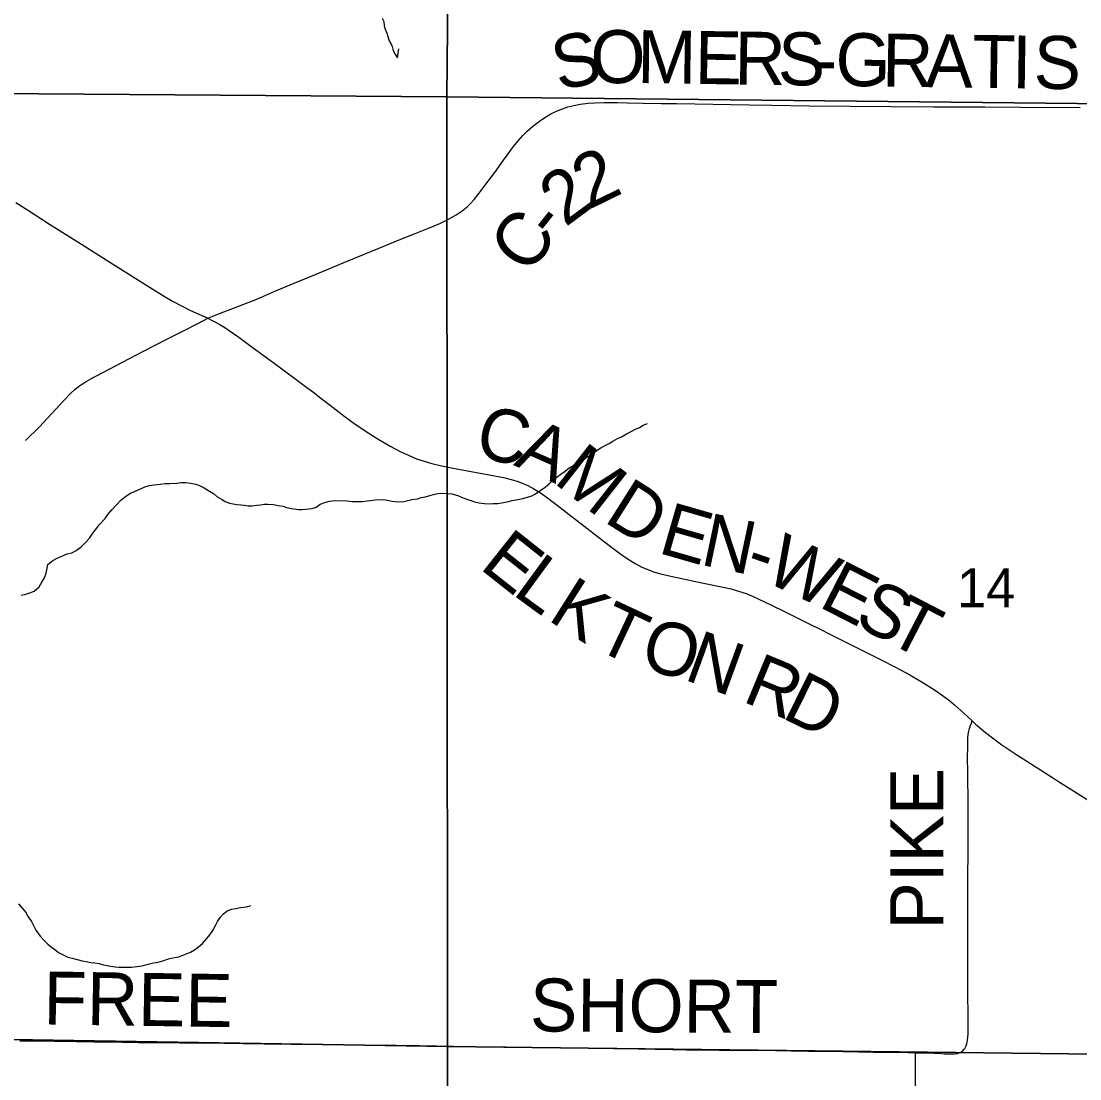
# Model space of a CAD drawing. Extents: x -8.8 to 41.4, y 0 to 34.6.
# Drawn here: x -7.904 to -6.769, y 15.544 to 16.678 of the extents above; entities that cross this region are included whole.
import ezdxf

# ---------------------------------------------------------------- set-up
doc = ezdxf.new("R2010")
doc.units = 0
for name, color, linetype in [('GM_X_Corporation', 7, 'Continuous'), ('GM_X_County_Road', 7, 'Continuous'), ('GM_X_Minor_River', 7, 'Continuous'), ('GM_X_Section_Text', 7, 'Continuous'), ('GM_X_Township_Road', 7, 'Continuous'), ('GM_X_Township_Road_Text', 7, 'Continuous'), ('GM_X_Township_Text', 7, 'Continuous')]:
    doc.layers.add(name, color=color, linetype=linetype)

msp = doc.modelspace()

# ---------------------------------------------------------------- linework, layer by layer
at = {"layer": 'GM_X_Corporation'}
for points in [[(-8.3984, 17.6086), (-7.4378, 17.5869), (-7.4474, 16.5968), (-8.42, 16.6037)], [(-7.4378, 17.5869), (-6.4092, 17.5696), (-6.4339, 16.586), (-7.4474, 16.5968)], [(-8.42, 16.6037), (-7.4474, 16.5968), (-7.4468, 15.5783), (-8.4261, 15.5941)], [(-7.4474, 16.5968), (-6.4339, 16.586), (-6.4479, 15.5667), (-7.4468, 15.5783)], [(-8.4261, 15.5941), (-7.4468, 15.5783), (-7.4475, 14.5649), (-8.4246, 14.5962)], [(-6.4479, 15.5667), (-6.4506, 14.5538), (-7.4475, 14.5649), (-7.4468, 15.5783)]]:
    msp.add_lwpolyline(points, close=True, dxfattribs=at)
at = {"layer": 'GM_X_County_Road'}
for points in [[(-7.7038, 16.3592), (-7.6912, 16.3642), (-7.6745, 16.3708), (-7.6514, 16.3799), (-7.6321, 16.3882), (-7.6051, 16.3993), (-7.5919, 16.4047), (-7.5586, 16.4186), (-7.5132, 16.4373), (-7.4987, 16.4432), (-7.4816, 16.4501), (-7.4671, 16.4558), (-7.4551, 16.461), (-7.4451, 16.4659), (-7.4374, 16.4702), (-7.4311, 16.4744), (-7.4258, 16.4788), (-7.4222, 16.4823), (-7.4184, 16.4865), (-7.413, 16.4933), (-7.4032, 16.5062), (-7.3962, 16.5157), (-7.3868, 16.5288), (-7.376, 16.5433), (-7.3711, 16.5496), (-7.3662, 16.5552), (-7.3614, 16.5599), (-7.3558, 16.5648), (-7.3495, 16.5697), (-7.3434, 16.5739), (-7.336, 16.5783), (-7.33, 16.5813), (-7.3237, 16.5839), (-7.3179, 16.5858), (-7.3113, 16.5875), (-7.3047, 16.5888), (-7.2961, 16.5899), (-7.2887, 16.5904), (-7.2788, 16.5906), (-7.2646, 16.5905), (-7.254, 16.5902), (-7.2372, 16.59), (-7.2177, 16.5897), (-7.2012, 16.5894), (-7.1232, 16.5882), (-7.099, 16.5878), (-7.0586, 16.5872), (-7.015, 16.5866), (-6.9716, 16.5863), (-6.9259, 16.586), (-6.9046, 16.5859), (-6.8709, 16.5858), (-6.8324, 16.5857), (-6.7685, 16.5853)], [(-7.9097, 16.4834), (-7.897, 16.4755), (-7.8735, 16.4603), (-7.8363, 16.4368), (-7.8126, 16.4219), (-7.7684, 16.3942), (-7.7495, 16.3824), (-7.7415, 16.3776), (-7.7312, 16.3721), (-7.7223, 16.3676), (-7.711, 16.3624), (-7.7038, 16.3592), (-7.7014, 16.3581), (-7.697, 16.3558), (-7.6909, 16.3525), (-7.6867, 16.35), (-7.682, 16.3468), (-7.6707, 16.339), (-7.6561, 16.3284), (-7.6341, 16.3122), (-7.6092, 16.2937), (-7.5977, 16.2851), (-7.5903, 16.2795), (-7.5839, 16.2746), (-7.5741, 16.267), (-7.5662, 16.2609), (-7.5564, 16.2534), (-7.5458, 16.2458), (-7.5376, 16.2402), (-7.5319, 16.2365), (-7.5203, 16.2293), (-7.5075, 16.2218), (-7.4976, 16.2165), (-7.4881, 16.212), (-7.4802, 16.2087), (-7.472, 16.2059), (-7.4637, 16.2035), (-7.4547, 16.2014), (-7.4388, 16.1983), (-7.4022, 16.1914), (-7.3869, 16.1884), (-7.3784, 16.1863), (-7.3712, 16.1841), (-7.3659, 16.1822), (-7.3608, 16.1799), (-7.3541, 16.1764), (-7.3472, 16.1721), (-7.3395, 16.1668), (-7.3262, 16.1565), (-7.3165, 16.1489), (-7.2738, 16.1159), (-7.2609, 16.1063), (-7.2522, 16.1004), (-7.2449, 16.0959), (-7.2384, 16.0924), (-7.2322, 16.0897), (-7.2258, 16.0875), (-7.2169, 16.085), (-7.2024, 16.0815), (-7.1811, 16.0771), (-7.1549, 16.0718), (-7.1428, 16.069), (-7.1349, 16.0668), (-7.1267, 16.064), (-7.1192, 16.0609), (-7.1129, 16.0581), (-7.0995, 16.0516), (-7.0855, 16.0448), (-7.0605, 16.0323), (-7.0466, 16.0254), (-7.0371, 16.0206), (-7.0149, 16.0096), (-6.9999, 16.0021), (-6.9826, 15.9935), (-6.9666, 15.9852), (-6.9513, 15.9769), (-6.9363, 15.968), (-6.9247, 15.9607), (-6.9149, 15.9541), (-6.9084, 15.9492), (-6.9032, 15.9448), (-6.893, 15.9356), (-6.8898, 15.9325), (-6.8842, 15.9275)], [(-6.8842, 15.9275), (-6.883, 15.9263), (-6.8807, 15.9241), (-6.8773, 15.9211), (-6.8719, 15.9164), (-6.8626, 15.9092), (-6.8526, 15.9019), (-6.8366, 15.8913), (-6.8109, 15.8749), (-6.7889, 15.8609), (-6.7563, 15.8403)]]:
    msp.add_lwpolyline(points, dxfattribs=at)
at = {"layer": 'GM_X_Minor_River'}
for points in [[(-7.517, 16.681), (-7.5152, 16.6775), (-7.5146, 16.6729), (-7.5136, 16.6694), (-7.5118, 16.6648), (-7.5094, 16.6568), (-7.5076, 16.6537), (-7.5062, 16.6506), (-7.5049, 16.6463), (-7.5027, 16.6417), (-7.5006, 16.6386), (-7.4991, 16.648)], [(-7.6685, 16.1592), (-7.6648, 16.1587), (-7.6606, 16.1581), (-7.6564, 16.158), (-7.6511, 16.1589), (-7.6473, 16.1592), (-7.6434, 16.1598), (-7.6396, 16.16), (-7.6332, 16.1594), (-7.6283, 16.1585), (-7.623, 16.1576), (-7.6189, 16.1563), (-7.6139, 16.1553), (-7.6064, 16.1543), (-7.6026, 16.1542), (-7.5919, 16.1553), (-7.5877, 16.1567), (-7.5834, 16.1599), (-7.5772, 16.162), (-7.5734, 16.163), (-7.5676, 16.1639), (-7.5544, 16.1635), (-7.549, 16.1629), (-7.5449, 16.1627), (-7.5384, 16.1629), (-7.5331, 16.1635), (-7.5293, 16.1637), (-7.5243, 16.1647), (-7.5151, 16.1651), (-7.5061, 16.1633), (-7.5, 16.1623), (-7.4936, 16.1628), (-7.4851, 16.1648), (-7.479, 16.1657), (-7.4752, 16.1671), (-7.4709, 16.1677), (-7.4667, 16.1687), (-7.4617, 16.1704), (-7.4571, 16.1714), (-7.4522, 16.1716), (-7.4472, 16.1714), (-7.4423, 16.1709), (-7.4359, 16.1691), (-7.4311, 16.167), (-7.4262, 16.1653), (-7.4217, 16.1637), (-7.4179, 16.1624), (-7.413, 16.1614), (-7.4073, 16.1605), (-7.4028, 16.1603), (-7.3978, 16.1605), (-7.3929, 16.1607), (-7.3891, 16.1613), (-7.3829, 16.1623), (-7.3776, 16.164), (-7.3715, 16.1649), (-7.3661, 16.1659), (-7.3622, 16.1672), (-7.3565, 16.1689), (-7.3526, 16.1711), (-7.3475, 16.1747), (-7.3436, 16.1772), (-7.3382, 16.1812), (-7.3342, 16.1853), (-7.3291, 16.1893), (-7.3252, 16.1922), (-7.3206, 16.1954), (-7.3163, 16.1987), (-7.3124, 16.2012), (-7.3077, 16.2041), (-7.3023, 16.2069), (-7.2972, 16.2106), (-7.2925, 16.213), (-7.2875, 16.2171), (-7.2824, 16.2203), (-7.2785, 16.2224), (-7.2735, 16.2249), (-7.2696, 16.2274), (-7.2646, 16.2303), (-7.2603, 16.2321), (-7.2549, 16.2353), (-7.2498, 16.2378), (-7.2452, 16.2403), (-7.2409, 16.242), (-7.2371, 16.2445), (-7.2324, 16.2463)], [(-7.9039, 16.0622), (-7.9001, 16.0632), (-7.8947, 16.065), (-7.8901, 16.0667), (-7.8846, 16.0711), (-7.8818, 16.0763), (-7.8789, 16.0811), (-7.8772, 16.086), (-7.8759, 16.0913), (-7.8754, 16.0951), (-7.8699, 16.0994), (-7.8652, 16.1019), (-7.8602, 16.104), (-7.8544, 16.1065), (-7.8494, 16.1078), (-7.8448, 16.1103), (-7.8397, 16.114), (-7.8346, 16.1191), (-7.8306, 16.1235), (-7.827, 16.1287), (-7.823, 16.1339), (-7.8198, 16.138), (-7.8139, 16.1446), (-7.8111, 16.1487), (-7.8063, 16.1542), (-7.802, 16.159), (-7.7969, 16.1642), (-7.7918, 16.1685), (-7.7867, 16.1718), (-7.7825, 16.1735), (-7.7774, 16.1756), (-7.7713, 16.1785), (-7.7663, 16.1798), (-7.7613, 16.1808), (-7.7548, 16.1813), (-7.7495, 16.1819), (-7.7445, 16.1821), (-7.7369, 16.1826), (-7.7327, 16.1832), (-7.7274, 16.183), (-7.7221, 16.1824), (-7.7168, 16.1815), (-7.7127, 16.1798), (-7.7078, 16.1773), (-7.7019, 16.1737), (-7.6978, 16.1713), (-7.6941, 16.1681), (-7.6892, 16.1653), (-7.6851, 16.1628), (-7.6806, 16.1611), (-7.6765, 16.1602), (-7.6727, 16.1597), (-7.6685, 16.1592)], [(-7.9067, 15.7314), (-7.9027, 15.7267), (-7.8987, 15.7216), (-7.8966, 15.7177), (-7.8933, 15.713), (-7.8908, 15.708), (-7.888, 15.7033), (-7.8836, 15.6967), (-7.8796, 15.6924), (-7.8752, 15.688), (-7.8715, 15.6849), (-7.8678, 15.6824), (-7.8637, 15.6793), (-7.854, 15.6743), (-7.8491, 15.673), (-7.8423, 15.6713), (-7.8386, 15.6704), (-7.8337, 15.6694), (-7.8291, 15.6685), (-7.825, 15.668), (-7.8204, 15.6674), (-7.8155, 15.6661), (-7.8118, 15.6652), (-7.808, 15.6647), (-7.8031, 15.6638), (-7.7993, 15.6633), (-7.7955, 15.6635), (-7.7906, 15.6633), (-7.7856, 15.6635), (-7.7772, 15.6647), (-7.7726, 15.6653), (-7.7676, 15.6667), (-7.7619, 15.668), (-7.7569, 15.669), (-7.7519, 15.6703), (-7.7461, 15.6724), (-7.7396, 15.6737), (-7.735, 15.6746), (-7.7296, 15.6767), (-7.7223, 15.6795), (-7.718, 15.682), (-7.7137, 15.6853), (-7.7094, 15.6889), (-7.7047, 15.6941), (-7.7015, 15.6982), (-7.6983, 15.7026), (-7.6954, 15.7082), (-7.6934, 15.7123), (-7.6906, 15.7168), (-7.687, 15.7205), (-7.6831, 15.7238), (-7.6785, 15.7255), (-7.6739, 15.7265), (-7.6689, 15.7274), (-7.6624, 15.7283), (-7.6578, 15.7297)]]:
    msp.add_lwpolyline(points, dxfattribs=at)
at = {"layer": 'GM_X_Township_Road'}
for points in [[(-7.8992, 16.2281), (-7.8844, 16.2429), (-7.8581, 16.2711), (-7.8508, 16.2788), (-7.8463, 16.283), (-7.8424, 16.2861), (-7.8383, 16.289), (-7.8341, 16.2915), (-7.8253, 16.2963), (-7.8149, 16.3018), (-7.7886, 16.3159), (-7.772, 16.3245), (-7.7476, 16.3368), (-7.7299, 16.3458), (-7.7139, 16.354), (-7.7038, 16.3592)], [(-6.945, 15.5717), (-6.933, 15.5715), (-6.9175, 15.5709), (-6.9144, 15.5707), (-6.9107, 15.5705), (-6.9068, 15.5704), (-6.9031, 15.5706), (-6.9, 15.571), (-6.8975, 15.5718), (-6.8958, 15.5728), (-6.8943, 15.5739), (-6.893, 15.5754), (-6.8923, 15.5763), (-6.8914, 15.5776), (-6.8907, 15.5792), (-6.8899, 15.5816), (-6.8892, 15.5853), (-6.8889, 15.5885), (-6.8887, 15.5915), (-6.8886, 15.6006), (-6.8888, 15.6155), (-6.889, 15.6314), (-6.889, 15.6501), (-6.889, 15.6709), (-6.889, 15.6818), (-6.889, 15.6979), (-6.889, 15.7116), (-6.889, 15.7221), (-6.8889, 15.7417), (-6.8889, 15.7606), (-6.8888, 15.7861), (-6.8888, 15.8103), (-6.8888, 15.8336), (-6.8888, 15.8501), (-6.8889, 15.8598), (-6.8891, 15.8722), (-6.8893, 15.8888), (-6.8891, 15.8986), (-6.889, 15.9091), (-6.8885, 15.9129), (-6.8879, 15.9166), (-6.8871, 15.9195), (-6.886, 15.9226), (-6.8851, 15.9251), (-6.8842, 15.9275)], [(-7.9054, 15.5845), (-7.8967, 15.5844), (-7.8905, 15.5844), (-7.8756, 15.5843), (-7.8682, 15.5842), (-7.8589, 15.5841), (-7.8446, 15.5838), (-7.826, 15.5834), (-7.7956, 15.583), (-7.7856, 15.5829), (-7.7782, 15.5828), (-7.7533, 15.5827), (-7.7335, 15.5824), (-7.7173, 15.5822), (-7.7074, 15.5821), (-7.695, 15.5822), (-7.6863, 15.5818), (-7.6664, 15.5815), (-7.6434, 15.5813), (-7.6279, 15.5811), (-7.6149, 15.5809), (-7.5807, 15.5806), (-7.5596, 15.5804), (-7.5472, 15.5802), (-7.526, 15.5799), (-7.5018, 15.5797), (-7.477, 15.5793), (-7.4404, 15.5789), (-7.4193, 15.5784), (-7.3839, 15.5779), (-7.3472, 15.5774), (-7.3274, 15.5772), (-7.3093, 15.5771), (-7.2808, 15.5765), (-7.2684, 15.5764), (-7.2615, 15.5764), (-7.2491, 15.5762), (-7.2423, 15.576), (-7.2361, 15.5759), (-7.2243, 15.5757), (-7.2175, 15.5756), (-7.2057, 15.5753), (-7.1988, 15.5752), (-7.1908, 15.575), (-7.1852, 15.575), (-7.1715, 15.5748), (-7.1554, 15.5745), (-7.1405, 15.5744), (-7.1218, 15.5743), (-7.0951, 15.5741), (-7.0783, 15.5738), (-7.0597, 15.5735), (-7.0516, 15.5733), (-7.0225, 15.573), (-6.9902, 15.5724), (-6.9734, 15.5722), (-6.9666, 15.5722), (-6.9529, 15.5719), (-6.945, 15.5717)], [(-6.9452, 15.5357), (-6.9451, 15.5547), (-6.945, 15.5651), (-6.945, 15.5717)]]:
    msp.add_lwpolyline(points, dxfattribs=at)

# ---------------------------------------------------------------- texts
at = {"layer": 'GM_X_Section_Text'}
for s, rotation, p in [('PIKE', 90, (-6.9154, 15.7039)), ('FREE', 359.1574, (-7.8802, 15.6021)), ('SHORT', 359.5955, (-7.3585, 15.5946))]:
    msp.add_text(s, height=0.05682, rotation=rotation, dxfattribs=at).set_placement(p)
at = {"layer": 'GM_X_Township_Road_Text'}
for s, rotation, p in [('S', 12.8507, (-7.3275, 16.6029)), ('O', 0.5209, (-7.2933, 16.6111)), ('M', 359.1833, (-7.2437, 16.6115)), ('E', 359.1814, (-7.182, 16.6106)), ('R', 359.1826, (-7.1395, 16.61)), ('S', 359.1832, (-7.0929, 16.6094)), ('G', 359.1826, (-7.0312, 16.6085)), ('R', 359.1826, (-6.9812, 16.6078)), ('A', 359.1826, (-6.9346, 16.6071)), ('T', 359.1824, (-6.8846, 16.6064)), ('I', 359.1855, (-6.8421, 16.6058)), ('S', 359.1827, (-6.8187, 16.6055)), ('-', 359.1803, (-7.0546, 16.6088)), ('2', 26.1362, (-7.2948, 16.4757)), ('2', 36.3641, (-7.3207, 16.4564)), ('C', 52.0747, (-7.3609, 16.4042)), ('-', 51.5078, (-7.3323, 16.4409)), ('C', 346.0279, (-7.4197, 16.2124)), ('A', 336.1411, (-7.3768, 16.202)), ('M', 321.8967, (-7.3343, 16.1837)), ('D', 327.7301, (-7.2806, 16.142)), ('E', 343.9417, (-7.2224, 16.1081)), ('N', 348.1026, (-7.1771, 16.0953)), ('E', 321.6377, (-7.4137, 16.0917)), ('W', 334.7469, (-7.1094, 16.0785)), ('L', 323.8216, (-7.3785, 16.0639)), ('-', 341.1911, (-7.13, 16.0854)), ('E', 332.87, (-7.0503, 16.0507)), ('K', 327.6973, (-7.3407, 16.0364)), ('S', 332.8612, (-7.0125, 16.0313)), ('T', 332.5859, (-6.9785, 16.0138)), ('T', 334.8451, (-7.2916, 16.006)), ('O', 346.104, (-7.2417, 15.9839)), ('N', 339.9265, (-7.1947, 15.9723)), ('R', 337.4825, (-7.1321, 15.9489)), ('D', 333.6854, (-7.0899, 15.9315))]:
    msp.add_text(s, height=0.0568, rotation=rotation, dxfattribs=at).set_placement(p)
at = {"layer": 'GM_X_Township_Text'}
msp.add_text('14', height=0.04186, rotation=0, dxfattribs=at).set_placement((-6.9005, 16.0493))

doc.saveas('drawing.dxf')
